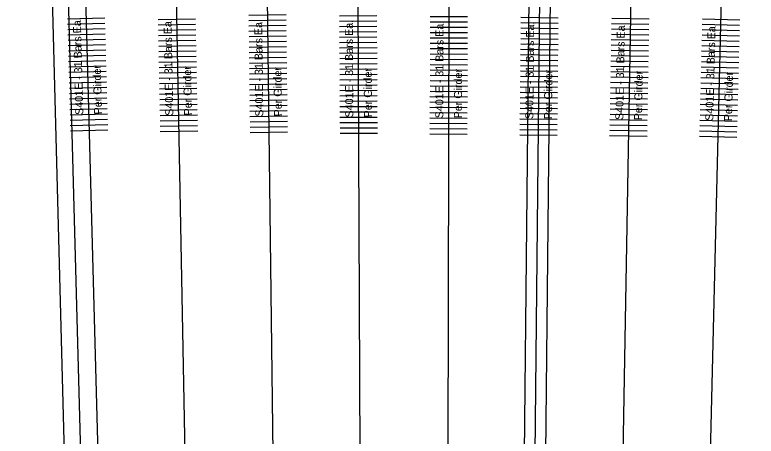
# Model space of a CAD drawing. Extents: x 632276 to 635000, y 381313 to 381846.
# Drawn here: x 634785.1 to 634854.6, y 381447.2 to 381486.6 of the extents above; entities that cross this region are included whole.
import ezdxf

# ---------------------------------------------------------------- set-up
doc = ezdxf.new("R2010")
doc.units = 0
for name, color, linetype in [('B_Boring Annot', 7, 'Continuous'), ('R_Border_Scale', 7, 'Continuous'), ('R_Road Edge of Shoulder', 7, 'Continuous'), ('R_Shade Removal', 7, 'Continuous'), ('R_Wall', 7, 'Continuous')]:
    doc.layers.add(name, color=color, linetype=linetype)

msp = doc.modelspace()

# ---------------------------------------------------------------- linework, layer by layer
at = {"layer": 'B_Boring Annot'}
for p, q in [((634832.38, 381395.621), (634835.411, 381700.486)), ((634834.38, 381395.601), (634837.411, 381700.466)), ((634785.119, 381621.102), (634790.932, 381401.034)), ((634786.619, 381621.142), (634792.431, 381401.073))]:
    msp.add_line(p, q, dxfattribs=at)
at = {"layer": 'R_Border_Scale'}
for p, q in [((634810.536, 381486.632), (634807.036, 381486.591)), ((634819.034, 381486.534), (634815.534, 381486.518)), ((634793.553, 381486.328), (634790.054, 381486.236)), ((634793.566, 381485.829), (634790.067, 381485.736)), ((634802.048, 381486.23), (634798.548, 381486.163)), ((634810.542, 381486.132), (634807.042, 381486.091)), ((634819.036, 381486.034), (634815.536, 381486.018)), ((634827.53, 381485.937), (634824.03, 381485.946)), ((634827.532, 381486.437), (634824.032, 381486.446)), ((634836.029, 381485.839), (634832.529, 381485.875)), ((634836.034, 381486.339), (634832.534, 381486.374)), ((634844.524, 381485.742), (634841.025, 381485.803)), ((634844.533, 381486.242), (634841.033, 381486.303)), ((634853.03, 381486.145), (634849.531, 381486.231)), ((634793.579, 381485.329), (634790.081, 381485.236)), ((634802.057, 381485.73), (634798.558, 381485.663)), ((634802.067, 381485.23), (634798.567, 381485.163)), ((634810.548, 381485.632), (634807.048, 381485.591)), ((634810.554, 381485.132), (634807.054, 381485.091)), ((634819.039, 381485.534), (634815.539, 381485.518)), ((634827.529, 381485.437), (634824.029, 381485.446)), ((634836.024, 381485.339), (634832.524, 381485.375)), ((634844.515, 381485.242), (634841.016, 381485.303)), ((634853.006, 381485.146), (634849.507, 381485.232)), ((634853.018, 381485.645), (634849.519, 381485.731)), ((634793.593, 381484.829), (634790.094, 381484.737)), ((634802.076, 381484.73), (634798.577, 381484.663)), ((634810.56, 381484.632), (634807.06, 381484.591)), ((634819.041, 381485.034), (634815.541, 381485.018)), ((634819.043, 381484.534), (634815.543, 381484.518)), ((634827.526, 381484.437), (634824.027, 381484.446)), ((634827.528, 381484.937), (634824.028, 381484.946)), ((634836.019, 381484.839), (634832.519, 381484.875)), ((634844.507, 381484.742), (634841.007, 381484.803)), ((634852.993, 381484.646), (634849.495, 381484.732)), ((634793.606, 381484.329), (634790.107, 381484.237)), ((634793.619, 381483.829), (634790.12, 381483.737)), ((634802.086, 381484.231), (634798.587, 381484.164)), ((634802.095, 381483.731), (634798.596, 381483.664)), ((634810.566, 381484.132), (634807.066, 381484.091)), ((634819.046, 381484.034), (634815.546, 381484.018)), ((634827.525, 381483.937), (634824.025, 381483.946)), ((634836.009, 381483.839), (634832.509, 381483.875)), ((634836.014, 381484.339), (634832.514, 381484.375)), ((634844.49, 381483.742), (634840.99, 381483.803)), ((634844.498, 381484.242), (634840.999, 381484.303)), ((634852.969, 381483.646), (634849.47, 381483.732)), ((634852.981, 381484.146), (634849.482, 381484.232)), ((634793.632, 381483.33), (634790.133, 381483.237)), ((634802.105, 381483.231), (634798.606, 381483.164)), ((634810.572, 381483.632), (634807.072, 381483.591)), ((634810.578, 381483.132), (634807.078, 381483.091)), ((634819.048, 381483.534), (634815.548, 381483.518)), ((634819.05, 381483.034), (634815.55, 381483.018)), ((634827.524, 381483.437), (634824.024, 381483.446)), ((634836.004, 381483.339), (634832.504, 381483.375)), ((634844.481, 381483.243), (634840.981, 381483.303)), ((634852.957, 381483.146), (634849.458, 381483.232)), ((634793.645, 381482.83), (634790.147, 381482.737)), ((634793.659, 381482.33), (634790.16, 381482.237)), ((634802.115, 381482.731), (634798.615, 381482.664)), ((634810.584, 381482.632), (634807.084, 381482.591)), ((634819.052, 381482.534), (634815.552, 381482.518)), ((634827.521, 381482.437), (634824.021, 381482.446)), ((634827.523, 381482.937), (634824.023, 381482.946)), ((634835.993, 381482.339), (634832.494, 381482.375)), ((634835.998, 381482.839), (634832.499, 381482.875)), ((634844.464, 381482.243), (634840.964, 381482.303)), ((634844.472, 381482.743), (634840.973, 381482.803)), ((634852.944, 381482.646), (634849.445, 381482.732)), ((634793.672, 381481.83), (634790.173, 381481.738)), ((634802.124, 381482.231), (634798.625, 381482.164)), ((634802.134, 381481.731), (634798.634, 381481.664)), ((634810.59, 381482.132), (634807.09, 381482.091)), ((634810.595, 381481.632), (634807.096, 381481.591)), ((634819.055, 381482.034), (634815.555, 381482.018)), ((634827.52, 381481.937), (634824.02, 381481.946)), ((634835.988, 381481.839), (634832.489, 381481.875)), ((634844.455, 381481.743), (634840.955, 381481.803)), ((634852.92, 381481.647), (634849.421, 381481.733)), ((634852.932, 381482.146), (634849.433, 381482.232)), ((634793.685, 381481.33), (634790.186, 381481.238)), ((634802.143, 381481.231), (634798.644, 381481.164)), ((634810.601, 381481.132), (634807.102, 381481.091)), ((634819.057, 381481.534), (634815.557, 381481.518)), ((634819.059, 381481.034), (634815.559, 381481.018)), ((634827.517, 381480.937), (634824.017, 381480.946)), ((634827.519, 381481.437), (634824.019, 381481.446)), ((634835.983, 381481.339), (634832.483, 381481.375)), ((634844.446, 381481.243), (634840.947, 381481.303)), ((634852.907, 381481.147), (634849.409, 381481.233)), ((634793.698, 381480.83), (634790.199, 381480.738)), ((634793.711, 381480.331), (634790.213, 381480.238)), ((634802.153, 381480.731), (634798.654, 381480.664)), ((634802.162, 381480.231), (634798.663, 381480.164)), ((634810.607, 381480.633), (634807.108, 381480.591)), ((634819.062, 381480.534), (634815.562, 381480.518)), ((634827.516, 381480.437), (634824.016, 381480.446)), ((634835.973, 381480.339), (634832.473, 381480.375)), ((634835.978, 381480.839), (634832.478, 381480.875)), ((634844.429, 381480.243), (634840.929, 381480.304)), ((634844.438, 381480.743), (634840.938, 381480.803)), ((634852.883, 381480.147), (634849.384, 381480.233)), ((634852.895, 381480.647), (634849.396, 381480.733)), ((634793.725, 381479.831), (634790.226, 381479.738)), ((634802.172, 381479.731), (634798.673, 381479.664)), ((634810.613, 381480.133), (634807.114, 381480.091)), ((634810.619, 381479.633), (634807.119, 381479.591)), ((634819.064, 381480.034), (634815.564, 381480.018)), ((634819.066, 381479.534), (634815.566, 381479.518)), ((634827.515, 381479.937), (634824.015, 381479.946)), ((634835.968, 381479.839), (634832.468, 381479.875)), ((634844.42, 381479.743), (634840.921, 381479.804)), ((634852.871, 381479.647), (634849.372, 381479.733)), ((634793.738, 381479.331), (634790.239, 381479.238)), ((634793.751, 381478.831), (634790.252, 381478.739)), ((634802.182, 381479.231), (634798.682, 381479.164)), ((634810.625, 381479.133), (634807.125, 381479.091)), ((634819.069, 381479.034), (634815.569, 381479.018)), ((634827.512, 381478.937), (634824.012, 381478.946)), ((634827.513, 381479.437), (634824.013, 381479.446)), ((634835.958, 381478.839), (634832.458, 381478.875)), ((634835.963, 381479.339), (634832.463, 381479.375)), ((634844.412, 381479.243), (634840.912, 381479.304)), ((634852.858, 381479.147), (634849.359, 381479.233)), ((634793.764, 381478.331), (634790.265, 381478.239)), ((634802.191, 381478.732), (634798.692, 381478.665)), ((634802.201, 381478.232), (634798.701, 381478.165)), ((634810.631, 381478.633), (634807.131, 381478.591)), ((634810.637, 381478.133), (634807.137, 381478.091)), ((634819.071, 381478.534), (634815.571, 381478.518)), ((634827.511, 381478.437), (634824.011, 381478.446)), ((634835.953, 381478.339), (634832.453, 381478.375)), ((634844.394, 381478.243), (634840.895, 381478.304)), ((634844.403, 381478.743), (634840.904, 381478.804)), ((634852.834, 381478.148), (634849.335, 381478.234)), ((634852.846, 381478.648), (634849.347, 381478.733)), ((634793.777, 381477.831), (634790.279, 381477.739)), ((634802.21, 381477.732), (634798.711, 381477.665)), ((634810.643, 381477.633), (634807.143, 381477.591)), ((634819.073, 381478.034), (634815.573, 381478.018)), ((634819.075, 381477.534), (634815.576, 381477.518)), ((634827.508, 381477.437), (634824.008, 381477.446)), ((634827.509, 381477.937), (634824.009, 381477.946)), ((634835.948, 381477.84), (634832.448, 381477.875)), ((634844.386, 381477.743), (634840.886, 381477.804)), ((634852.821, 381477.648), (634849.323, 381477.734)), ((634793.791, 381477.332), (634790.292, 381477.239)), ((634793.804, 381476.832), (634790.305, 381476.739)), ((634802.22, 381477.232), (634798.721, 381477.165)), ((634810.649, 381477.133), (634807.149, 381477.091)), ((634819.078, 381477.034), (634815.578, 381477.018)), ((634827.507, 381476.937), (634824.007, 381476.946)), ((634835.938, 381476.84), (634832.438, 381476.875)), ((634835.943, 381477.34), (634832.443, 381477.375)), ((634844.368, 381476.744), (634840.869, 381476.804)), ((634844.377, 381477.243), (634840.878, 381477.304)), ((634852.809, 381477.148), (634849.31, 381477.234)), ((634793.817, 381476.332), (634790.318, 381476.24)), ((634802.229, 381476.732), (634798.73, 381476.665)), ((634802.239, 381476.232), (634798.74, 381476.165)), ((634810.655, 381476.633), (634807.155, 381476.591)), ((634810.661, 381476.133), (634807.161, 381476.091)), ((634819.08, 381476.534), (634815.58, 381476.518)), ((634827.505, 381476.437), (634824.005, 381476.446)), ((634835.933, 381476.34), (634832.433, 381476.375)), ((634844.36, 381476.244), (634840.86, 381476.304)), ((634852.785, 381476.148), (634849.286, 381476.234)), ((634852.797, 381476.648), (634849.298, 381476.734)), ((634793.83, 381475.832), (634790.331, 381475.74)), ((634802.249, 381475.732), (634798.749, 381475.665)), ((634810.667, 381475.633), (634807.167, 381475.591)), ((634819.082, 381476.034), (634815.582, 381476.018)), ((634819.085, 381475.534), (634815.585, 381475.518)), ((634827.503, 381475.437), (634824.003, 381475.446)), ((634827.504, 381475.937), (634824.004, 381475.946)), ((634835.923, 381475.34), (634832.423, 381475.375)), ((634835.928, 381475.84), (634832.428, 381475.875)), ((634844.351, 381475.744), (634840.852, 381475.804)), ((634852.772, 381475.648), (634849.273, 381475.734)), ((634844.342, 381475.244), (634840.843, 381475.304)), ((634852.76, 381475.149), (634849.261, 381475.235))]:
    msp.add_line(p, q, dxfattribs=at)
at = {"layer": 'R_Road Edge of Shoulder'}
msp.add_line((634833.143, 381371.836), (634836.411, 381700.476), dxfattribs=at)
at = {"layer": 'R_Shade Removal'}
for p, q in [((634788.244, 381621.071), (634794.056, 381401.003)), ((634801.93, 381400.924), (634797.718, 381620.977)), ((634807.191, 381620.883), (634809.805, 381400.846)), ((634817.68, 381400.768), (634816.665, 381620.789)), ((634826.138, 381620.694), (634825.554, 381400.689)), ((634845.095, 381620.506), (634841.305, 381400.533)), ((634849.179, 381400.454), (634854.569, 381620.412))]:
    msp.add_line(p, q, dxfattribs=at)

# ---------------------------------------------------------------- texts
at = {"layer": 'R_Wall'}
for s, rotation, p in [('S401E - 31 Bars Ea,', 91.52278, (634791.541, 381477.272)), ('S401E - 31 Bars Ea,', 91.10681, (634799.97, 381477.189)), ('S401E - 31 Bars Ea,', 90.69065, (634808.399, 381477.106)), ('S401E - 31 Bars Ea,', 90.27437, (634816.828, 381477.024)), ('S401E - 31 Bars Ea,', 89.85799, (634825.257, 381476.943)), ('S401E - 31 Bars Ea,', 89.43036, (634833.688, 381476.862)), ('S401E - 31 Bars Ea,', 89.01848, (634842.119, 381476.782)), ('S401E - 31 Bars Ea,', 88.60208, (634850.548, 381476.703)), ('Per Girder', 91.52278, (634793.291, 381477.319)), ('Per Girder', 91.10681, (634801.72, 381477.222)), ('Per Girder', 90.69065, (634810.149, 381477.127)), ('Per Girder', 90.27437, (634818.578, 381477.032)), ('Per Girder', 89.85799, (634827.007, 381476.938)), ('Per Girder', 89.43036, (634835.438, 381476.845)), ('Per Girder', 89.01848, (634843.868, 381476.752)), ('Per Girder', 88.60208, (634852.297, 381476.661))]:
    msp.add_text(s, height=0.75, rotation=rotation, dxfattribs=at).set_placement(p)

doc.saveas('drawing.dxf')
